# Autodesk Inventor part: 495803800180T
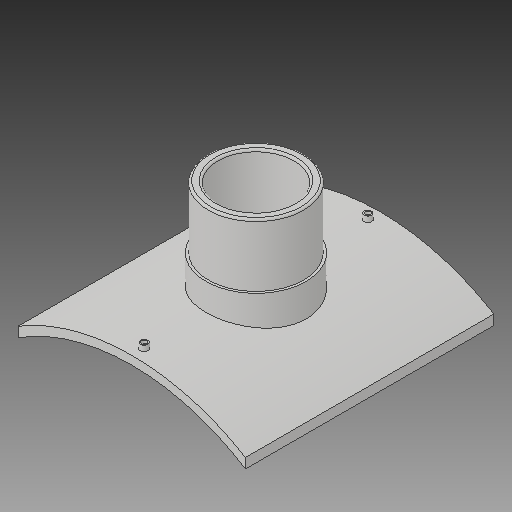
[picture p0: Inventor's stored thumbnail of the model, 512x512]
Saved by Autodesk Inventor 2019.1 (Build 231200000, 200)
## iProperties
Created: 2017-10
Part Number: 495803800180T
Material: Generic
Description: PLASSON BRANCH SADDLE  800x180
Document SubType Name: Modeling
Designer: KIM
Mass: 2754.05 g
Surface Area: 3037.44 cm^2
Volume: 2754.05 cm^3
Density: 1 g/cm^3
Appearance: Default
Author: KIM
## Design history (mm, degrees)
derived "495803.ipt"
feature "Solid1::495803.ipt"
tag "TaggingFeature1"
body "Solid1"
other parameters: "d1" = 16, "d4" = 0, "d12" = 425.6, "d13" = 14, "d14" = 211.5, "d16" = 5 deg, "d18" = 4, "d19" = 14, "d20" = 0, "d21" = 3, "d22" = 0, "d23" = 585, "d24" = 189, "d25" = 16, "d26" = 144, "d28" = 0, "d29" = 9.6, "d31" = 0, "d32" = 84.5, "d33" = 0, "d34" = 8, "d37" = 118.3, "d38" = 0, "d39" = 4, "H_" = 169, "x_" = 16, "D_" = 16
